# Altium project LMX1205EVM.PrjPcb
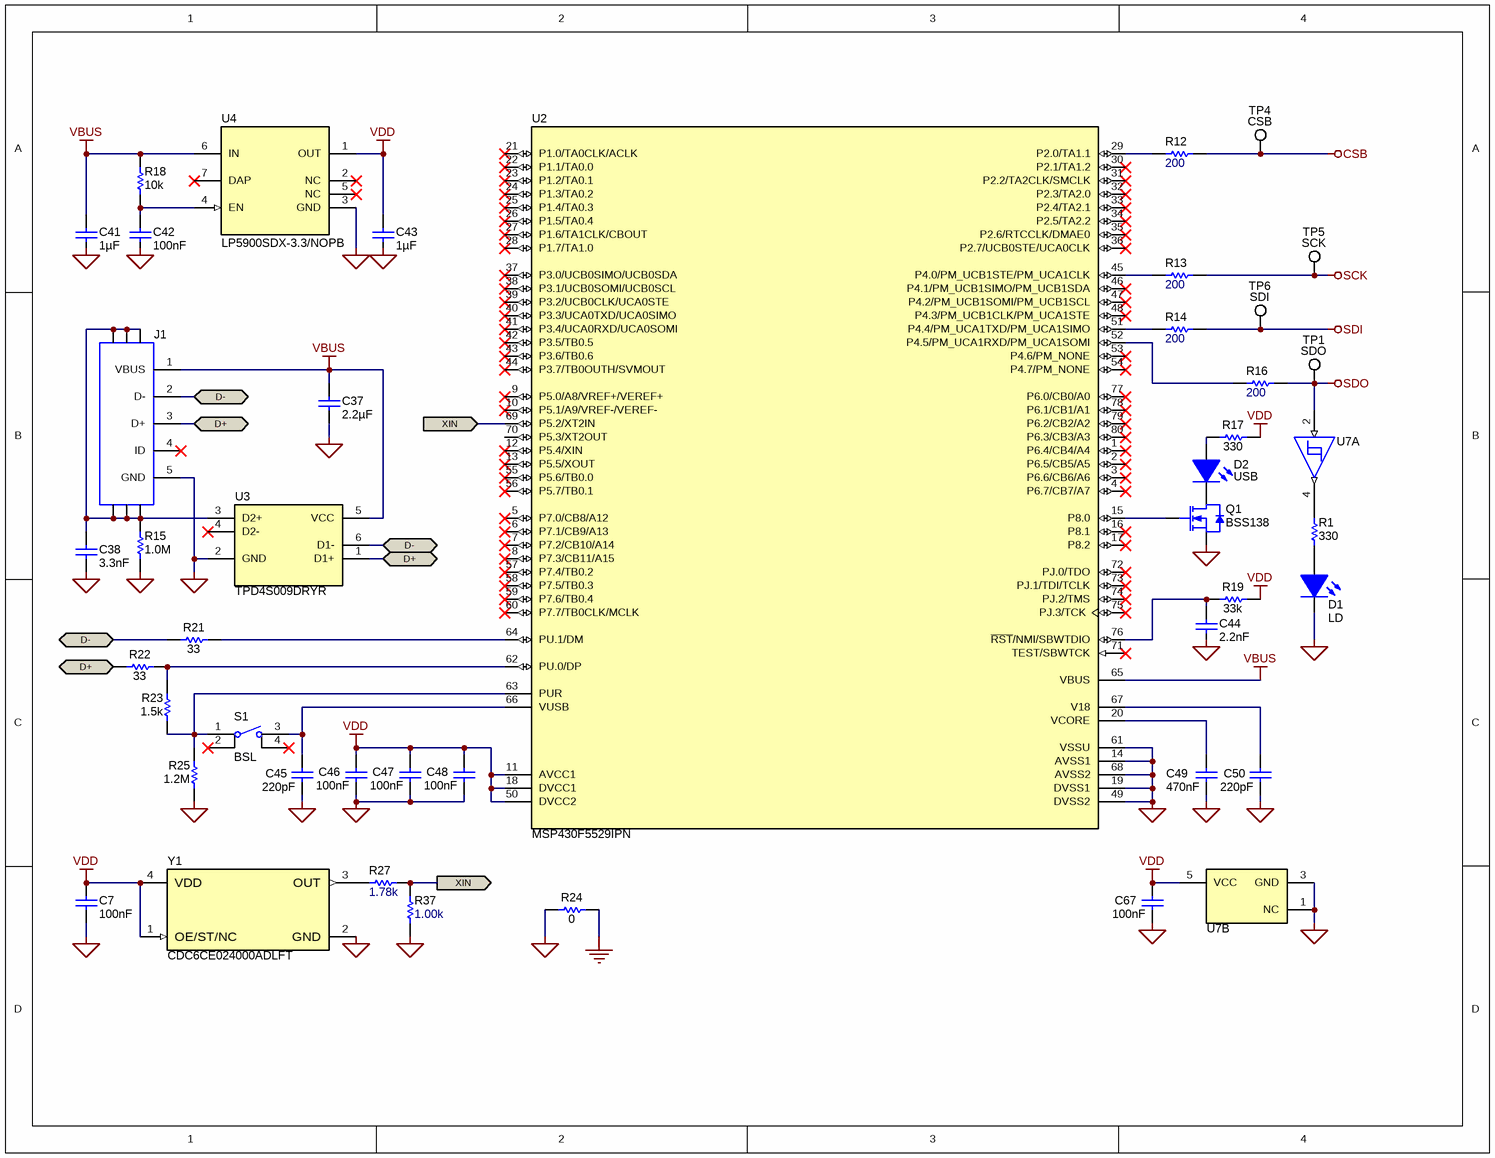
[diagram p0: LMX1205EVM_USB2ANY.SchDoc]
TID: N/A; TechSupport: http://www.ti.com/support; SCH_Rev: B; PRJ_Title: LMX1205EVM; PRJ_Customer: Public Release; PCB_Rev: B; CopyrightYear: 2024
4 sheets, 176 parts. Net scope: flat (ports and power ports of the same name join across sheets).
Board file: LMX1205EVM.PcbDoc
Sheets:
  LMX1205EVM_USB2ANY.SchDoc
  LMX1205EVM_PWR.SchDoc
  LMX1205EVM_BUF.SchDoc
  LMX1205EVM_Hardware.SchDoc

## Sheet LMX1205EVM_USB2ANY.SchDoc: USB2ANY
size Letter; Date: Not shown in title block; ApprovedBy: Not shown in title block; CheckedBy: Not shown in title block; Author: Not shown in title block; CompanyName: Not shown in title block; DrawnBy: Noel Fung; Engineer: Noel Fung; Organization: Not shown in title block; Address1: Not shown in title block; Address2: Not shown in title block; Address3: Not shown in title block; Address4: Not shown in title block; DocumentNumber: 1; Revision: Use project parameter SCH_Rev; SheetNumber: 1; SheetTotal: 4; PageSetup: Record=PageOptions¦CenterHorizontal=True¦CenterVertical=True¦PrintScale=1.00¦XCorrection=1.00¦YCorrection=1.00¦PrintKind=0¦BorderSize=5000000¦LeftOffset=0¦BottomOffset=0¦Orientation=2¦PaperLength=1000¦PaperWidth=1000¦Scale=100¦PaperSource=15¦PrintQuality=600¦MediaType=1¦DitherType=10¦PaperKind=Letter¦PrintScaleMode=1

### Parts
C7  Cap_F: 100nF  [0603]  (hidden comment: 885012206046)
C37  Cap_F: 2.2µF  [0603]  (hidden comment: 885012106018)
C38  Cap_F: 3.3nF  [0603]  (hidden comment: 885012206086)
C41  Cap_F: 1µF  [0603]  (hidden comment: 885012206052)
C42  Cap_F: 100nF  [0603]  (hidden comment: 885012206046)
C43  Cap_F: 1µF  [0603]  (hidden comment: 885012206052)
C44  Cap_F: 2.2nF  [0603]  (hidden comment: 885012206036)
C45  ValueDisplayed: 220pF  [0603]  (hidden comment: C0603C221J5GACTU)
C46  Cap_F: 100nF  [0603]  (hidden comment: 885012206046)
C47  Cap_F: 100nF  [0603]  (hidden comment: 885012206046)
C48  Cap_F: 100nF  [0603]  (hidden comment: 885012206046)
C49  Cap_F: 470nF  [0603]  (hidden comment: GRM188R71C474KA88D)
C50  ValueDisplayed: 220pF  [0603]  (hidden comment: C0603C221J5GACTU)
C67  Cap_F: 100nF  [0603]  (hidden comment: 885012206046)
D1  LD  [LED_LTST-C190]
D2  USB  [LED_LTST-C190]
J1  10118194-0001LF  [FCI_10118194-0001LF]  (value not drawn)
Q1  BSS138  [SOT-23]
R1  ValueDisplayed: 330  [0603]  (hidden comment: CRCW0603330RJNEA)
R12  ValueDisplayed: 200  [0603]  (hidden comment: CRCW0603200RFKEA)
R13  ValueDisplayed: 200  [0603]  (hidden comment: CRCW0603200RFKEA)
R14  ValueDisplayed: 200  [0603]  (hidden comment: CRCW0603200RFKEA)
R15  ValueDisplayed: 1.0M  [0603]  (hidden comment: CRCW06031M00JNEA)
R16  ValueDisplayed: 200  [0603]  (hidden comment: CRCW0603200RFKEA)
R17  ValueDisplayed: 330  [0603]  (hidden comment: CRCW0603330RJNEA)
R18  ValueDisplayed: 10k  [0603]  (hidden comment: CRCW060310K0JNEA)
R19  ValueDisplayed: 33k  [0603]  (hidden comment: CRCW060333K0JNEA)
R21  ValueDisplayed: 33  [0603]  (hidden comment: CRCW060333R0JNEA)
R22  ValueDisplayed: 33  [0603]  (hidden comment: CRCW060333R0JNEA)
R23  ValueDisplayed: 1.5k  [0603]  (hidden comment: CRCW06031K50JNEA)
R24  ValueDisplayed: 0  [0603]  (hidden comment: CRCW06030000Z0EA)
R25  ValueDisplayed: 1.2M  [0603]  (hidden comment: CRCW06031M20JNEA)
R27  ValueDisplayed: 1.78k  [0402]  (hidden comment: CRCW04021K78FKED)
R37  ValueDisplayed: 1.00k  [0402]  (hidden comment: CRCW04021K00FKED)
S1  BSL  [SW_FSM4JSMA]
TP1  SDO  [Keystone5002]
TP4  CSB  [Keystone5002]
TP5  SCK  [Keystone5002]
TP6  SDI  [Keystone5002]
U2  MSP430F5529IPN  [PN0080A_N]
U3  TPD4S009DRYR  [DRY0006A]
U4  LP5900SDX-3.3/NOPB  [NGF0006A]
U7  SN74LVC1G17DBVR  [DBV0005A_N]  (value not drawn)  (parts A,B of 2)
Y1  PartNumber: CDC6CE024000ADLFT  [DLF0004A-MFG]  (hidden comment: CDC6CXXXXXXXDLFT)

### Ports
D+ (bidir), D- (bidir), XIN (in), XIN (out)

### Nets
CSB: R12.2 TP4.1
DGND: C7.2 C37.2 C38.2 C41.2 C42.2 C43.2 C44.2 C45.2 C46.2 C47.2 C48.2 C49.2 C50.2 C67.2 D1.2(K) J1.5(GND) Q1.2(S) R15.1 R24.1 R25.1 R37.1 U2.14(AVSS1) U2.19(DVSS1) U2.49(DVSS2) U2.61(VSSU) U2.68(AVSS2) U3.2(GND) U4.3(GND) U7.1(NC) U7.3(GND) Y1.2(GND)
GND: R24.2
SCK: R13.2 TP5.1
SDI: R14.2 TP6.1
SDO: R16.2 TP1.1 U7.2(A)
VBUS: C37.1 C41.1 J1.1(VBUS) R18.2 U2.65(VBUS) U3.5(VCC) U4.6(IN)
VDD: C7.1 C43.1 C46.1 C47.1 C48.1 C67.1 R17.2 R19.2 U2.11(AVCC1) U2.18(DVCC1) U2.50(DVCC2) U4.1(OUT) U7.5(VCC) Y1.1(OE/ST/NC) Y1.4(VDD)
D+: J1.3(D+) R22.1 U3.1(D1+) ; port D+
D-: J1.2(D-) R21.1 U3.6(D1-) ; port D-
XIN: R27.2 R37.2 U2.69(P5.2/XT2IN) ; port XIN
NetC38_1: C38.1 J1.6 J1.7 J1.8 J1.9 J1.10 J1.11 R15.2 U3.3(D2+)
NetC42_1: C42.1 R18.1 U4.4(EN)
NetC44_1: C44.1 R19.1 U2.76(~{RST}/NMI/SBWTDIO)
NetC45_1: C45.1 S1.3 U2.66(VUSB)
NetC49_1: C49.1 U2.20(VCORE)
NetC50_1: C50.1 U2.67(V18)
NetD1_1: D1.1(A) R1.1
NetD2_1: D2.1(A) R17.1
NetD2_2: D2.2(K) Q1.3(D)
NetQ1_1: Q1.1(G) U2.15(P8.0)
NetR1_2: R1.2 U7.4(Y)
NetR12_1: R12.1 U2.29(P2.0/TA1.1)
NetR13_1: R13.1 U2.45(P4.0/PM_UCB1STE/PM_UCA1CLK)
NetR14_1: R14.1 U2.51(P4.4/PM_UCA1TXD/PM_UCA1SIMO)
NetR16_1: R16.1 U2.52(P4.5/PM_UCA1RXD/PM_UCA1SOMI)
NetR21_2: R21.2 U2.64(PU.1/DM)
NetR22_2: R22.2 R23.2 U2.62(PU.0/DP)
NetR23_1: R23.1 R25.2 S1.1 U2.63(PUR)
NetR27_1: R27.1 Y1.3(OUT)

Not connected (* = marked no-connect by the designer): J1 4(ID)*; S1 2* 4*; U2 1(P6.4/CB4/A4)* 2(P6.5/CB5/A5)* 3(P6.6/CB6/A6)* 4(P6.7/CB7/A7)* 5(P7.0/CB8/A12)* 6(P7.1/CB9/A13)* 7(P7.2/CB10/A14)* 8(P7.3/CB11/A15)* 9(P5.0/A8/VREF+/VEREF+)* 10(P5.1/A9/VREF-/VEREF-)* 12(P5.4/XIN)* 13(P5.5/XOUT)* 16(P8.1)* 17(P8.2)* 21(P1.0/TA0CLK/ACLK)* 22(P1.1/TA0.0)* 23(P1.2/TA0.1)* 24(P1.3/TA0.2)* 25(P1.4/TA0.3)* 26(P1.5/TA0.4)* 27(P1.6/TA1CLK/CBOUT)* 28(P1.7/TA1.0)* 30(P2.1/TA1.2)* 31(P2.2/TA2CLK/SMCLK)* 32(P2.3/TA2.0)* 33(P2.4/TA2.1)* 34(P2.5/TA2.2)* 35(P2.6/RTCCLK/DMAE0)* 36(P2.7/UCB0STE/UCA0CLK)* 37(P3.0/UCB0SIMO/UCB0SDA)* 38(P3.1/UCB0SOMI/UCB0SCL)* 39(P3.2/UCB0CLK/UCA0STE)* 40(P3.3/UCA0TXD/UCA0SIMO)* 41(P3.4/UCA0RXD/UCA0SOMI)* 42(P3.5/TB0.5)* 43(P3.6/TB0.6)* 44(P3.7/TB0OUTH/SVMOUT)* 46(P4.1/PM_UCB1SIMO/PM_UCB1SDA)* 47(P4.2/PM_UCB1SOMI/PM_UCB1SCL)* 48(P4.3/PM_UCB1CLK/PM_UCA1STE)* 53(P4.6/PM_NONE)* 54(P4.7/PM_NONE)* 55(P5.6/TB0.0)* 56(P5.7/TB0.1)* 57(P7.4/TB0.2)* 58(P7.5/TB0.3)* 59(P7.6/TB0.4)* 60(P7.7/TB0CLK/MCLK)* 70(P5.3/XT2OUT) 71(TEST/SBWTCK)* 72(PJ.0/TDO)* 73(PJ.1/TDI/TCLK)* 74(PJ.2/TMS)* 75(PJ.3/TCK)* 77(P6.0/CB0/A0)* 78(P6.1/CB1/A1)* 79(P6.2/CB2/A2)* 80(P6.3/CB3/A3)*; U3 4(D2-)*; U4 2(NC)* 5(NC)* 7(DAP)*

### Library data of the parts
C7 C42 C46-C48 C67 = CMP-0006829-4: CAP, CERM, 0.1 uF, 16 V, +/- 10%, X7R, 0603; Manufacturer: Wurth Elektronik; TaMin_C: -55°C; Polarized: N; SizeAreaWB_mm2: 4.68; Value1: Unknown; U/M: EA; Value: 0.1uF; TaMax_C: 125°C; SizeZ_mm: 1; SizeX_mm: 1.6; SizeY_mm: 0.8; Value2: 16V; SizeArea_mm2: 1.28; AEC Category: Q200
C37 = CMP-0006825-5: CAP, CERM, 2.2 uF, 16 V, +/- 20%, X5R, 0603; Manufacturer: Wurth Elektronik; TaMin_C: -55°C; Polarized: N; SizeAreaWB_mm2: 4.68; Value1: Unknown; U/M: EA; Value: 2.2uF; TaMax_C: 85°C; SizeZ_mm: 1; SizeX_mm: 1.6; SizeY_mm: 0.8; Value2: 16V; SizeArea_mm2: 1.28; AEC Category: Q200
C38 = CMP-0077942-1: CAP, CERM, 3300 pF, 50 V,+/- 10%, X7R, 0603; Manufacturer: Wurth Elektronik; TaMin_C: -55°C; Polarized: N; SizeAreaWB_mm2: 4.68; U/M: EA; Value: 3300pF; TaMax_C: 125°C; SizeZ_mm: 1; SizeX_mm: 1.6; SizeY_mm: 0.8; Value2: 50V; SizeArea_mm2: 1.28; AEC Category: Q200
C41 C43 = CMP-0006831-4: CAP, CERM, 1 uF, 16 V, +/- 10%, X7R, 0603; Manufacturer: Wurth Elektronik; TaMin_C: -55°C; Polarized: N; SizeAreaWB_mm2: 4.68; Value1: Unknown; U/M: EA; Value: 1uF; TaMax_C: 125°C; SizeZ_mm: 1; SizeX_mm: 1.6; SizeY_mm: 0.8; Value2: 16V; SizeArea_mm2: 1.28; AEC Category: Q200
C44 = CMP-0006827-4: CAP, CERM, 2200 pF, 16 V, +/- 10%, X7R, 0603; Manufacturer: Wurth Elektronik; TaMin_C: -55°C; Polarized: N; SizeAreaWB_mm2: 4.68; Value1: Unknown; U/M: EA; Value: 2200pF; TaMax_C: 125°C; SizeZ_mm: 1; SizeX_mm: 1.6; SizeY_mm: 0.8; Value2: 16V; SizeArea_mm2: 1.28; AEC Category: Q200
C45 C50 = CMP-0006893-4: CAP, CERM, 220 pF, 50 V, +/- 5%, C0G/NP0, 0603; Manufacturer: Kemet; TaMin_C: -55°C; Polarized: N; SizeAreaWB_mm2: 4.68; Value1: Unknown; U/M: EA; Value: 220pF; TaMax_C: 125°C; SizeZ_mm: 1; SizeX_mm: 1.6; SizeY_mm: 0.8; Value2: 50V; SizeArea_mm2: 1.28; AEC Category: Q200
C49 = CMP-0007398-4: CAP, CERM, 0.47 uF, 16 V, +/- 10%, X7R, 0603; Manufacturer: MuRata; TaMin_C: -55°C; Polarized: N; SizeAreaWB_mm2: 4.68; Value1: Unknown; U/M: EA; Value: 0.47uF; TaMax_C: 125°C; SizeZ_mm: 1; SizeX_mm: 1.6; SizeY_mm: 0.8; Value2: 16V; SizeArea_mm2: 1.28; AEC Category: Q200
D1 D2 = CMP-0002827-3: LED, Green, SMD; Manufacturer: Lite-On; PartNumber: LTST-C190GKT; Power_TotalModule: 100mW; Value2: 2.1V; Io_A: 20mA; Value1: 0.1W
J1 = CMP-0074596-2: Receptacle, USB 2.0, Micro-USB Type B, R/A, SMT; Manufacturer: FCI; CNHeader: False; Current_A: 1.8A; Gender: Female; Voltage_V: 100V; Row_Count: 1; Pitch_mm: 0.65; ContactFinish: Gold; CT: True; Cert_UL: Y
Q1 = CMP-0000755-1: MOSFET, N-CH, 50 V, 0.22 A, SOT-23; Alternate Manufacturer: None; Manufacturer: Fairchild Semiconductor; SizeZ_mm: 1.1; ChType: N; Value2: 1.7 nC; VdsMax_V: 50V; SizeX_mm: 2.5; SizeY_mm: 3; Vgs_V: 20V; Value: 50V; Rdson45_ohm: 6; SizeArea_mm2: 7.5; AEC Category: Q101; IdsMax_A: 220mA; SizeAreaWB_mm2: 14; U/M: EA; QgTyp_nC: 1.7
R1 R17 = CMP-0025785-4: RES, 330, 5%, 0.1 W, AEC-Q200 Grade 0, 0603; Manufacturer: Vishay-Dale; Power_W: 100mW; TempCo: 200 ppm/C; Value_Code: 330R; Value: 330; EIA_Code: E24; SizeX_mm: 1.6; SizeY_mm: 0.8; SizeZ_mm: 1; Value2: 0.1W; SizeArea_mm2: 1.28; AEC Qualified: Y; VDC_V: 75V; AEC Category: Q200; AEC Grade: 0
R12-R14 R16 = CMP-0022201-5: RES, 200, 1%, 0.1 W, AEC-Q200 Grade 0, 0603; Manufacturer: Vishay-Dale; Power_W: 100mW; TempCo: 100 ppm/C; Value_Code: 200R; Value: 200; EIA_Code: E96; SizeX_mm: 1.6; SizeY_mm: 0.8; SizeZ_mm: 1; Value2: 0.1W; SizeArea_mm2: 1.28; AEC Qualified: Y; VDC_V: 75V; AEC Category: Q200; AEC Grade: 0
R15 = CMP-0025736-4: RES, 1.0 M, 5%, 0.1 W, AEC-Q200 Grade 0, 0603; Manufacturer: Vishay-Dale; Power_W: 100mW; TempCo: 200 ppm/C; Value_Code: 1M00; Value: 1.0Meg; EIA_Code: E24; Res_ohm: 1M; SizeX_mm: 1.6; SizeY_mm: 0.8; SizeZ_mm: 1; Value2: 0.1W; SizeArea_mm2: 1.28; AEC Qualified: Y; VDC_V: 75V; AEC Category: Q200; AEC Grade: 0
R18 = CMP-0025701-4: RES, 10 k, 5%, 0.1 W, AEC-Q200 Grade 0, 0603; Manufacturer: Vishay-Dale; Power_W: 100mW; TempCo: 200 ppm/C; Value_Code: 10k0; Value: 10k; EIA_Code: E24; SizeX_mm: 1.6; SizeY_mm: 0.8; SizeZ_mm: 1; Value2: 0.1W; SizeArea_mm2: 1.28; AEC Qualified: Y; VDC_V: 75V; AEC Category: Q200; AEC Grade: 0
R19 = CMP-0025786-4: RES, 33 k, 5%, 0.1 W, AEC-Q200 Grade 0, 0603; Manufacturer: Vishay-Dale; Power_W: 100mW; TempCo: 200 ppm/C; Value_Code: 33k0; Value: 33k; EIA_Code: E24; SizeX_mm: 1.6; SizeY_mm: 0.8; SizeZ_mm: 1; Value2: 0.1W; SizeArea_mm2: 1.28; AEC Qualified: Y; VDC_V: 75V; AEC Category: Q200; AEC Grade: 0
R21 R22 = CMP-0025787-4: RES, 33, 5%, 0.1 W, AEC-Q200 Grade 0, 0603; Manufacturer: Vishay-Dale; Power_W: 100mW; TempCo: 200 ppm/C; Value_Code: 33R0; Value: 33; EIA_Code: E24; SizeX_mm: 1.6; SizeY_mm: 0.8; SizeZ_mm: 1; Value2: 0.1W; SizeArea_mm2: 1.28; AEC Qualified: Y; VDC_V: 75V; AEC Category: Q200; AEC Grade: 0
R23 = CMP-0025733-4: RES, 1.5 k, 5%, 0.1 W, AEC-Q200 Grade 0, 0603; Manufacturer: Vishay-Dale; Power_W: 100mW; TempCo: 200 ppm/C; Value_Code: 1k50; Value: 1.5k; EIA_Code: E24; SizeX_mm: 1.6; SizeY_mm: 0.8; SizeZ_mm: 1; Value2: 0.1W; SizeArea_mm2: 1.28; AEC Qualified: Y; VDC_V: 75V; AEC Category: Q200; AEC Grade: 0
R24 = CMP-0025697-4: RES, 0, 5%, 0.1 W, AEC-Q200 Grade 0, 0603; Manufacturer: Vishay-Dale; Power_W: 100mW; TempCo: 200 ppm/C; Value_Code: 0000; Value: 0; EIA_Code: E24; SizeX_mm: 1.6; SizeY_mm: 0.8; SizeZ_mm: 1; Value2: 0.1W; SizeArea_mm2: 1.28; AEC Qualified: Y; VDC_V: 75V; AEC Category: Q200
R25 = CMP-0025738-4: RES, 1.2 M, 5%, 0.1 W, AEC-Q200 Grade 0, 0603; Manufacturer: Vishay-Dale; Power_W: 100mW; TempCo: 200 ppm/C; Value_Code: 1M20; Value: 1.2Meg; EIA_Code: E24; SizeX_mm: 1.6; SizeY_mm: 0.8; SizeZ_mm: 1; Value2: 0.1W; SizeArea_mm2: 1.28; AEC Qualified: Y; VDC_V: 75V; AEC Category: Q200; AEC Grade: 0
R27 = CMP-0026095-2: RES, 1.78 k, 1%, 0.063 W, AEC-Q200 Grade 0, 0402; Manufacturer: Vishay-Dale; Power_W: 63mW; TempCo: 100 ppm/C; Value_Code: 1k78; Value: 1.78k; EIA_Code: E96; SizeX_mm: 1; SizeY_mm: 0.5; SizeZ_mm: 0.6; Value2: 0.063W; AEC Qualified: Y; VDC_V: 50V; AEC Category: Q200; AEC Grade: 0
R37 = CMP-0026071-3: RES, 1.00 k, 1%, 0.063 W, AEC-Q200 Grade 0, 0402; Manufacturer: Vishay-Dale; Power_W: 63mW; TempCo: 100 ppm/C; Value_Code: 1k00; Value: 1.00k; EIA_Code: E96; Res_ohm: 1k; SizeX_mm: 1; SizeY_mm: 0.5; SizeZ_mm: 0.6; Value2: 0.063W; AEC Qualified: Y; VDC_V: 50V; AEC Category: Q200; AEC Grade: 0
S1 = CMP-0002134-3: Switch, Tactile, SPST-NO, 0.05A, 12V, SMT; PartNumber: FSM4JSMA; Manufacturer: TE Connectivity; CurrentRating_mA: 50A; PositionCount: 1; SwitchFunction: Off-Mom
TP1 TP4-TP6 = CMP-0055139-2: Test Point, Miniature, White, TH; Manufacturer: Keystone Electronics; CNHeader: FALSE; Green_Lifecycle: Active; Green_REACh: Passed; ContactFinish: Silver; CT: TRUE
U2 = CMP-0038965-1: 25 MHz Mixed Signal Microcontroller with 128 KB Flash, 8192 B SRAM and 63 GPIOs, -40 to 85 degC, 80-pin QFP (PN), Green (RoHS & no Sb/Br); Manufacturer: Texas Instruments; Real-Time Clock: Yes; Multiplier: 32x32; Frequency(MHz): 25; USCI_A (UART/LIN/IrDA/SPI): 2; SubFamily: 5 Series; Timers - 16-bit: 4; ADC Channels: 16; GPIO: 63; SRAM(B): 8192; DMA: 3; ADC: 12-bit SAR; Flash(KB): 128; USB: 1
U3 = CMP-0043120-3: 4-Channel ESD Solution for High-Speed Differential Interface, DRY0006A (USON-6); Manufacturer: Texas Instruments; Eco-Plan: Green (RoHS & no Sb/Br); Differential Capacitance(pF): 0.05; IEC 61000-4-2 Contact(+/- kV): 8; IO Capacitance(Typ)(pF): 0.8; Breakdown Voltage(Min)(V): 9; IO Leakage Current(nA): Jan-00; AEC Category: Q200; AEC Qualified: N; CompType: IC; SizeAreaWB_mm2: 4.9; SizeArea_mm2: 1.45; SizeX_mm: 1.0; SizeZ_mm: 0.6; Rating: Catalog
U4 = CMP-0070655-2: Ultra Low Noise, 150mA Linear Regulator for RF/Analog Circuits Requires No Bypass Capacitor, 6-pin LLP, Pb-Free; Manufacturer: Texas Instruments; PackageTopMarking: XTT*L16; CompType: LDO IC; PowerWise: N
U7 = CMP-0051702-2: Single Schmitt-Trigger Buffer, DBV0005A, LARGE T&R; Manufacturer: Texas Instruments; Output Drive (IOL/IOH)(Max)(mA): 32/-32; Technology Family: LVC; ICC @ Nom Voltage(Max)(mA): 0.01; VCC(Min)(V): 1.65; F @ Nom Voltage(Max)(Mhz): 150; Schmitt Trigger: Yes; Voltage(Nom)(V): 1.8,2.5,3.3,5; 3-State Output: No; Bits(#): 1; VCC(Max)(V): 5.5; Input Type: CMOS/TTL; Logic: True; tpd @ Nom Voltage(Max)(ns): 11,6.5,5.5,5; Output Type: CMOS; Rating: Catalog; Sub-Family: Non-Inverting Buffer/Driver; AEC Category: Q200; AEC Qualified: N; CompType: IC; SizeX_mm: 2.8; SizeY_mm: 2.9; SizeZ_mm: 1.45
Y1 = CMP-0097145-1: High-Performance BAW Oscillator; Manufacturer: Texas Instruments; Alternate PartNumber: LMK6CE02400CDLF; Min Supply Voltage: 1.62V; Frequency Stability: 25ppm; AEC Qualified: No; Max Supply Voltage: 3.63V; Standoff Height: 0mm; SizeZ_mm: 1mm; TJmax_C: +130°C

## Sheet LMX1205EVM_PWR.SchDoc: PowerSupply
size Letter; Date: Not shown in title block; ApprovedBy: Not shown in title block; CheckedBy: Not shown in title block; Author: Not shown in title block; CompanyName: Not shown in title block; DrawnBy: Noel Fung; Engineer: Noel Fung; Organization: Not shown in title block; Address1: Not shown in title block; Address2: Not shown in title block; Address3: Not shown in title block; Address4: Not shown in title block; DocumentNumber: 2; Revision: Use project parameter SCH_Rev; SheetNumber: 2; SheetTotal: 4; PageSetup: Record=PageOptions¦CenterHorizontal=True¦CenterVertical=True¦PrintScale=1.00¦XCorrection=1.00¦YCorrection=1.00¦PrintKind=0¦BorderSize=5000000¦LeftOffset=0¦BottomOffset=0¦Orientation=2¦PaperLength=1000¦PaperWidth=1000¦Scale=100¦PaperSource=15¦PrintQuality=600¦MediaType=1¦DitherType=10¦PaperKind=Letter¦PrintScaleMode=1
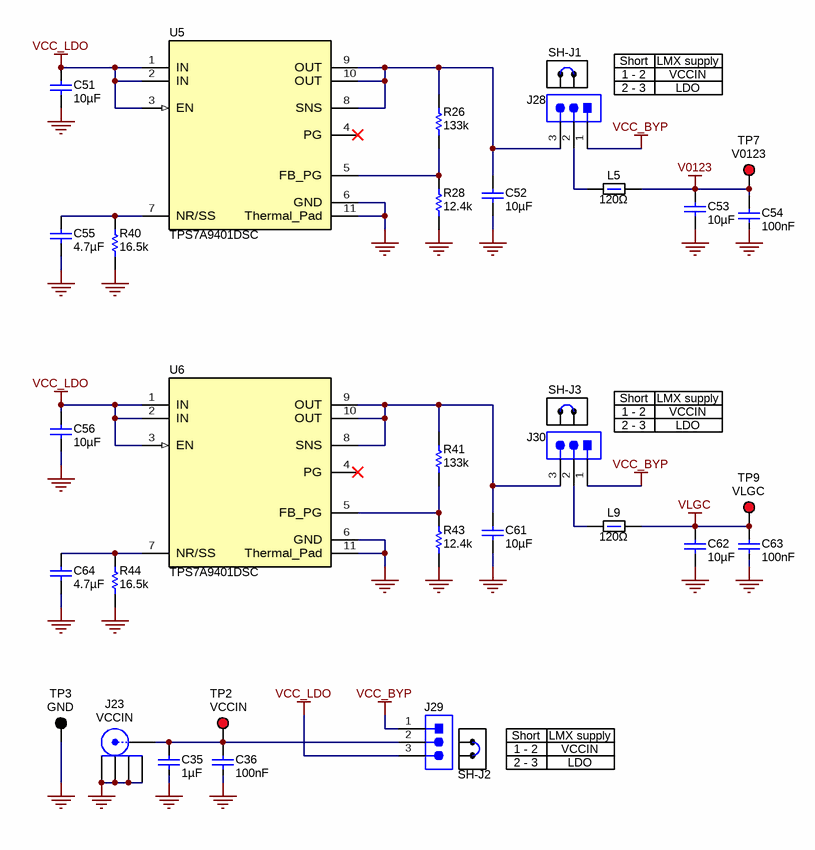
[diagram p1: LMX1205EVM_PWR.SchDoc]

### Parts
C35  Cap_F: 1µF  [0603]  (hidden comment: 885012206052)
C36  Cap_F: 100nF  [0603]  (hidden comment: 885012206046)
C51  ValueDisplayed: 10µF  [0603]  (hidden comment: GRM188R61A106KAALD)
C52  ValueDisplayed: 10µF  [0603]  (hidden comment: GRM188R61A106KAALD)
C53  ValueDisplayed: 10µF  [0603]  (hidden comment: GRM188R61A106KAALD)
C54  Cap_F: 100nF  [0603]  (hidden comment: 885012206046)
C55  Cap_F: 4.7µF  [0603]  (hidden comment: GRM188Z71C475KE21D)
C56  ValueDisplayed: 10µF  [0603]  (hidden comment: GRM188R61A106KAALD)
C61  ValueDisplayed: 10µF  [0603]  (hidden comment: GRM188R61A106KAALD)
C62  ValueDisplayed: 10µF  [0603]  (hidden comment: GRM188R61A106KAALD)
C63  Cap_F: 100nF  [0603]  (hidden comment: 885012206046)
C64  Cap_F: 4.7µF  [0603]  (hidden comment: GRM188Z71C475KE21D)
J23  VCCIN  [FP-CON-SMA-EDGE-S_CONN_JACK-MFG]
J28  TSW-103-07-G-S  [TSW-103-07-G-S]  (value not drawn)
J29  TSW-103-07-G-S  [TSW-103-07-G-S]  (value not drawn)
J30  TSW-103-07-G-S  [TSW-103-07-G-S]  (value not drawn)
L5  120Ω  [0603]
L9  120Ω  [0603]
R26  ValueDisplayed: 133k  [0603]  (hidden comment: CRCW0603133KFKEA)
R28  ValueDisplayed: 12.4k  [0603]  (hidden comment: CRCW060312K4FKEA)
R40  ValueDisplayed: 16.5k  [0603]  (hidden comment: CRCW060316K5FKEA)
R41  ValueDisplayed: 133k  [0603]  (hidden comment: CRCW0603133KFKEA)
R43  ValueDisplayed: 12.4k  [0603]  (hidden comment: CRCW060312K4FKEA)
R44  ValueDisplayed: 16.5k  [0603]  (hidden comment: CRCW060316K5FKEA)
SH-J1  SNT-100-BK-G  [SNT-100-BK-G]  (value not drawn)
SH-J2  SNT-100-BK-G  [SNT-100-BK-G]  (value not drawn)
SH-J3  SNT-100-BK-G  [SNT-100-BK-G]  (value not drawn)
TP2  VCCIN  [Keystone5000]
TP3  GND  [Keystone5001]
TP7  V0123  [Keystone5000]
TP9  VLGC  [Keystone5000]
U5  TPS7A9401DSC  [DSC0010J-MFG]
U6  TPS7A9401DSC  [DSC0010J-MFG]

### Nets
GND: C35.2 C36.2 C51.2 C52.2 C53.1 C54.2 C55.2 C56.2 C61.2 C62.1 C63.2 C64.2 J23.2 J23.3 J23.4 J23.5 R28.1 R40.1 R43.1 R44.1 TP3.1 U5.6(GND) U5.11(Thermal_Pad) U6.6(GND) U6.11(Thermal_Pad)
V0123: C53.2 C54.1 L5.2 TP7.1
VCC_BYP: J28.1 J29.1 J30.1
VCC_LDO: C51.1 C56.1 J29.3 U5.1(IN) U5.2(IN) U5.3(EN) U6.1(IN) U6.2(IN) U6.3(EN)
VLGC: C62.2 C63.1 L9.2 TP9.1
NetC35_1: C35.1 C36.1 J23.1 J29.2 TP2.1
NetC52_1: C52.1 J28.3 R26.2 U5.8(SNS) U5.9(OUT) U5.10(OUT)
NetC55_1: C55.1 R40.2 U5.7(NR/SS)
NetC61_1: C61.1 J30.3 R41.2 U6.8(SNS) U6.9(OUT) U6.10(OUT)
NetC64_1: C64.1 R44.2 U6.7(NR/SS)
NetJ28_2: J28.2 L5.1
NetJ30_2: J30.2 L9.1
NetR26_1: R26.1 R28.2 U5.5(FB_PG)
NetR41_1: R41.1 R43.2 U6.5(FB_PG)

Not connected (* = marked no-connect by the designer): U5 4(PG)*; U6 4(PG)*

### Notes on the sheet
- Short
- 1 - 2
- LMX supply
- VCCIN
- 2 - 3
- LDO
- (near SH-J2) Short
- (near SH-J2) 1 - 2
- (near SH-J2) 2 - 3

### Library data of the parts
C35 = CMP-0006831-4: as C41 on sheet LMX1205EVM_USB2ANY
C36 C54 C63 = CMP-0006829-4: as C7 on sheet LMX1205EVM_USB2ANY
C51-C53 C56 C61 C62 = CMP-0086193-1: CAP, CERM, 10 µF, 10 V,+/- 10%, X5R, 0603; Manufacturer: MuRata; SizeY_mm: 0.8; SizeAreaWB_mm2: 4.68; SizeX_mm: 1.6; SizeArea_mm2: 1.28; VDC_V: 10V; AEC Qualified: N; Value: 10uF; U/M: EA; SizeZ_mm: 1; TaMax_C: 85°C; AEC Category: Q200; TaMin_C: -55°C
C55 C64 = CMP-0064936-4: CAP, CERM, 4.7 uF, 16 V,+/- 10%, X7R, 0603; Manufacturer: MuRata; TaMin_C: -55°C; Polarized: N; SizeAreaWB_mm2: 4.68; Value1: Unknown; U/M: EA; Value: 4.7uF; TaMax_C: 125°C; SizeZ_mm: 1; SizeX_mm: 1.6; SizeY_mm: 0.8; Value2: 16V; SizeArea_mm2: 1.28; AEC Category: Q200
J23 = CMP-0088000-4: CONN SMA JACK STR EDGE MNT; Manufacturer: RF Solutions Ltd.; PartNumber: CON-SMA-EDGE-S; ContactFinish: Gold; Shrouded: true
J28-J30 = CMP-0075407-2: Header, 100mil, 3x1, Gold, TH; Manufacturer: Samtec; Pitch_mm: 2.54; Cert_VDE: N; Gender: Male; Cert_CSA: Y; Voltage_V: 550V; Green_REACh: Passed; Current_A: 6.3A; Green_Lifecycle: Active; Row_Count: 1
L5 L9 = CMP-0003352-2: Ferrite Bead, 120 ohm @ 100 MHz, 3 A, 0603; Manufacturer: MuRata; PartNumber: BLM18SG121TN1D; ZTyp@100MHz_Ohm: 120; SizeAreaWB_mm2: 4.68; DCR_ohm: 0.025; Value1: 0.025 ohm; Value: 120 ohm; Imax_A: 3A; SizeZ_mm: 1; SizeX_mm: 1.6; SizeY_mm: 0.8; SizeArea_mm2: 1.28
R26 R41 = CMP-0022038-4: RES, 133 k, 1%, 0.1 W, AEC-Q200 Grade 0, 0603; Manufacturer: Vishay-Dale; Power_W: 100mW; TempCo: 100 ppm/C; Value: 133k; EIA_Code: E96; SizeX_mm: 1.6; SizeY_mm: 0.8; SizeZ_mm: 1; Value2: 0.1W; SizeArea_mm2: 1.28; AEC Qualified: Y; VDC_V: 75V; AEC Category: Q200; AEC Grade: 0
R28 R43 = CMP-0022031-4: RES, 12.4 k, 1%, 0.1 W, AEC-Q200 Grade 0, 0603; Manufacturer: Vishay-Dale; Power_W: 100mW; TempCo: 100 ppm/C; Value_Code: 12k4; Value: 12.4k; EIA_Code: E96; SizeX_mm: 1.6; SizeY_mm: 0.8; SizeZ_mm: 1; Value2: 0.1W; SizeArea_mm2: 1.28; AEC Qualified: Y; VDC_V: 75V; AEC Category: Q200; AEC Grade: 0
R40 R44 = CMP-0022080-4: RES, 16.5 k, 1%, 0.1 W, AEC-Q200 Grade 0, 0603; Manufacturer: Vishay-Dale; Power_W: 100mW; TempCo: 100 ppm/C; Value_Code: 16k5; Value: 16.5k; EIA_Code: E96; SizeX_mm: 1.6; SizeY_mm: 0.8; SizeZ_mm: 1; Value2: 0.1W; SizeArea_mm2: 1.28; AEC Qualified: Y; VDC_V: 75V; AEC Category: Q200; AEC Grade: 0
SH-J1-SH-J3 = CMP-0003623-3: Shunt, 100mil, Gold plated, Black; Alternate PartNumber: 969102-0000-DA; Manufacturer: Samtec; Alternate Manufacturer: 3M; Value: 1x2; Note: You can "mate" this to a header by matching the designator.  i.e. use SH-J3 for header J3
TP2 TP7 TP9 = CMP-0055137-2: Test Point, Miniature, Red, TH; Manufacturer: Keystone Electronics; CNHeader: FALSE; Green_Lifecycle: Active; Green_REACh: Passed; ContactFinish: Silver; CT: TRUE
TP3 = CMP-0055138-2: Test Point, Miniature, Black, TH; Manufacturer: Keystone Electronics; CNHeader: FALSE; Green_Lifecycle: Active; Green_REACh: Passed; ContactFinish: Silver; CT: TRUE
U5 U6 = CMP-0091022-1: 1-A, Ultra-Low Noise, Ultra-High PSRR, RF Voltage Regulator; Manufacturer: Texas Instruments; Max Supply Voltage: 5.5V; Accuracy Percentage: 1-1.5%; SizeZ_mm: 0.8mm; Output Type: AdjustableProgrammable; Min Supply Voltage: 1.7V; TJmax_C: +150°C; Dropout Voltage: 210mV; AEC Qualified: No; Standoff Height: 0mm; Output Voltage: 0.4-5.3V; Number Of Outputs: 1; Nominal Supply Current: 15-47mA

## Sheet LMX1205EVM_BUF.SchDoc: RF Buffer
size Letter; Date: Not shown in title block; ApprovedBy: Not shown in title block; CheckedBy: Not shown in title block; Author: Not shown in title block; CompanyName: Not shown in title block; DrawnBy: Noel Fung; Engineer: Noel Fung; Organization: Not shown in title block; Address1: Not shown in title block; Address2: Not shown in title block; Address3: Not shown in title block; Address4: Not shown in title block; DocumentNumber: 3; Revision: Use project parameter SCH_Rev; SheetNumber: 3; SheetTotal: 4; PageSetup: Record=PageOptions¦CenterHorizontal=True¦CenterVertical=True¦PrintScale=1.00¦XCorrection=1.00¦YCorrection=1.00¦PrintKind=0¦BorderSize=5000000¦LeftOffset=0¦BottomOffset=0¦Orientation=2¦PaperLength=1000¦PaperWidth=1000¦Scale=100¦PaperSource=15¦PrintQuality=600¦MediaType=1¦DitherType=10¦PaperKind=Letter¦PrintScaleMode=1
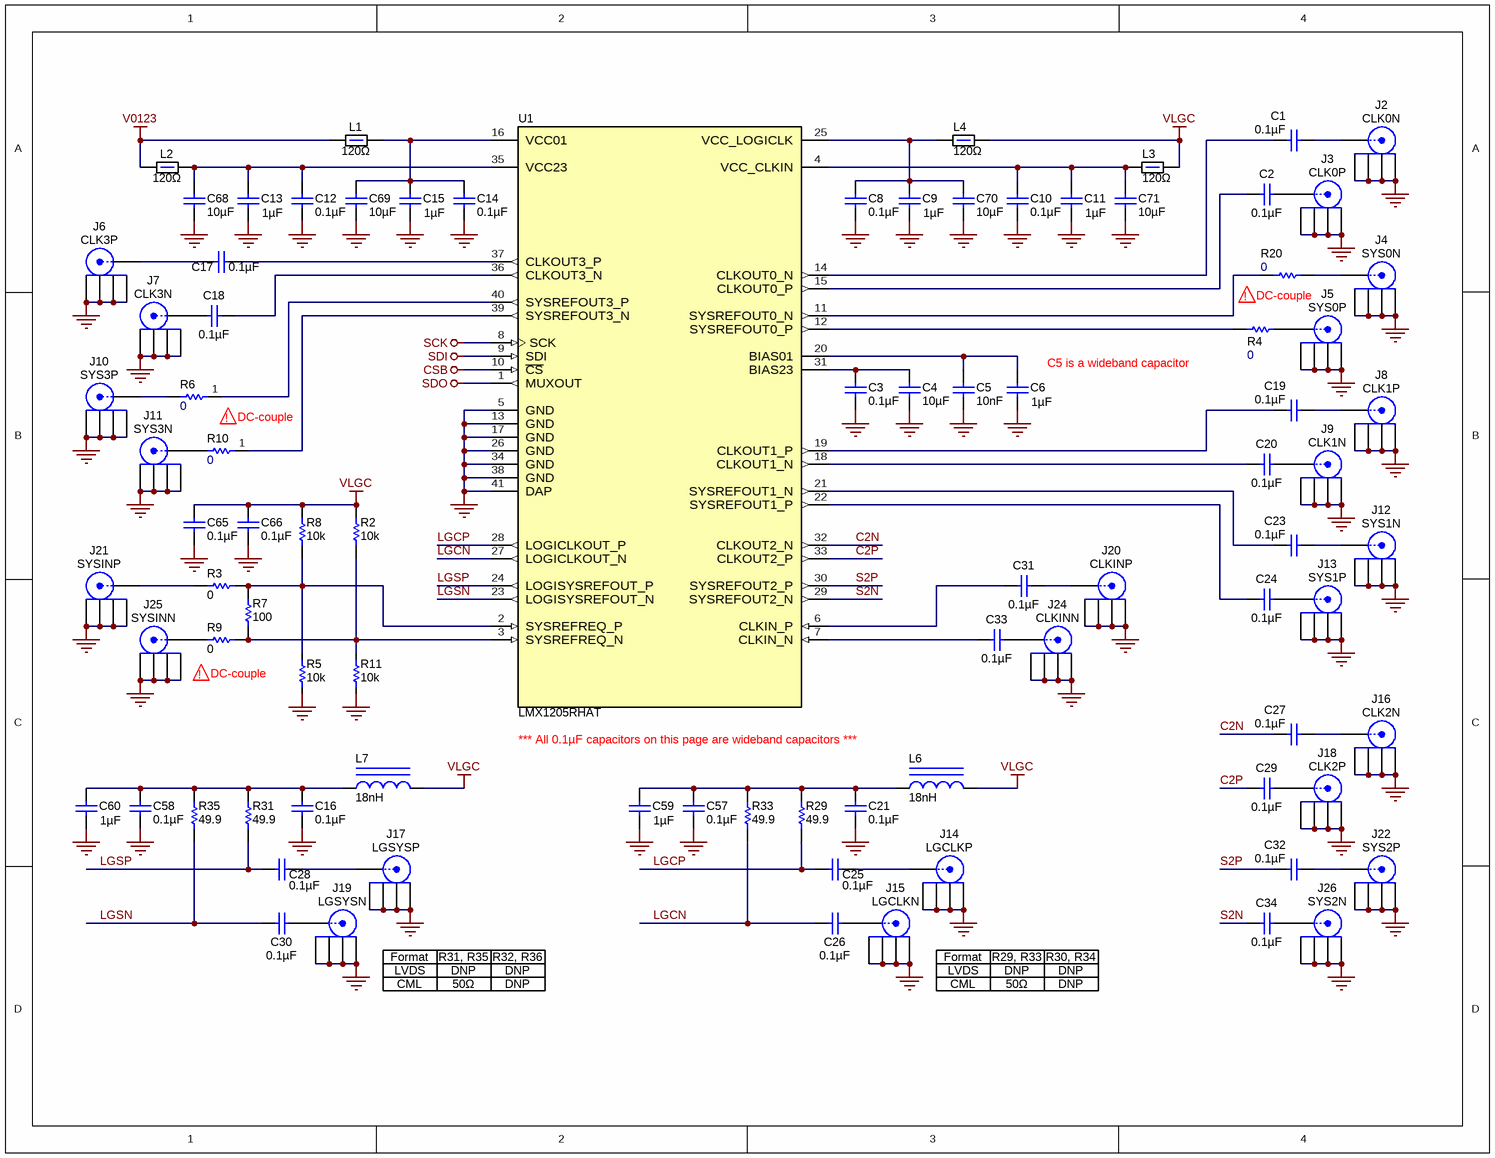
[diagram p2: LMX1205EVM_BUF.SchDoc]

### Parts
C1  ValueDisplayed: 0.1µF  [0201_033L]  (hidden comment: ATC530Z104KT10T)
C2  ValueDisplayed: 0.1µF  [0201_033L]  (hidden comment: ATC530Z104KT10T)
C3  ValueDisplayed: 0.1µF  [0201_033L]  (hidden comment: ATC530Z104KT10T)
C4  ValueDisplayed: 10µF  [0603L]  (hidden comment: GRM188R61A106KAALD)
C5  ValueDisplayed: 10nF  [0201_033L]  (hidden comment: 550Z103PTT)
C6  ValueDisplayed: 1µF  [0402S]  (hidden comment: GRM155R61E105KA12D)
C8  ValueDisplayed: 0.1µF  [0201_033L]  (hidden comment: ATC530Z104KT10T)
C9  ValueDisplayed: 1µF  [0402S]  (hidden comment: GRM155R61E105KA12D)
C10  ValueDisplayed: 0.1µF  [0201_033L]  (hidden comment: ATC530Z104KT10T)
C11  ValueDisplayed: 1µF  [0402S]  (hidden comment: GRM155R61E105KA12D)
C12  ValueDisplayed: 0.1µF  [0201_033L]  (hidden comment: ATC530Z104KT10T)
C13  ValueDisplayed: 1µF  [0402S]  (hidden comment: GRM155R61E105KA12D)
C14  ValueDisplayed: 0.1µF  [0201_033L]  (hidden comment: ATC530Z104KT10T)
C15  ValueDisplayed: 1µF  [0402S]  (hidden comment: GRM155R61E105KA12D)
C16  ValueDisplayed: 0.1µF  [0201_033L]  (hidden comment: ATC530Z104KT10T)
C17  ValueDisplayed: 0.1µF  [0201_033L]  (hidden comment: ATC530Z104KT10T)
C18  ValueDisplayed: 0.1µF  [0201_033L]  (hidden comment: ATC530Z104KT10T)
C19  ValueDisplayed: 0.1µF  [0201_033L]  (hidden comment: ATC530Z104KT10T)
C20  ValueDisplayed: 0.1µF  [0201_033L]  (hidden comment: ATC530Z104KT10T)
C21  ValueDisplayed: 0.1µF  [0201_033L]  (hidden comment: ATC530Z104KT10T)
C23  ValueDisplayed: 0.1µF  [0201_033L]  (hidden comment: ATC530Z104KT10T)
C24  ValueDisplayed: 0.1µF  [0201_033L]  (hidden comment: ATC530Z104KT10T)
C25  ValueDisplayed: 0.1µF  [0201_033L]  (hidden comment: ATC530Z104KT10T)
C26  ValueDisplayed: 0.1µF  [0201_033L]  (hidden comment: ATC530Z104KT10T)
C27  ValueDisplayed: 0.1µF  [0201_033L]  (hidden comment: ATC530Z104KT10T)
C28  ValueDisplayed: 0.1µF  [0201_033L]  (hidden comment: ATC530Z104KT10T)
C29  ValueDisplayed: 0.1µF  [0201_033L]  (hidden comment: ATC530Z104KT10T)
C30  ValueDisplayed: 0.1µF  [0201_033L]  (hidden comment: ATC530Z104KT10T)
C31  ValueDisplayed: 0.1µF  [0201_033L]  (hidden comment: ATC530Z104KT10T)
C32  ValueDisplayed: 0.1µF  [0201_033L]  (hidden comment: ATC530Z104KT10T)
C33  ValueDisplayed: 0.1µF  [0201_033L]  (hidden comment: ATC530Z104KT10T)
C34  ValueDisplayed: 0.1µF  [0201_033L]  (hidden comment: ATC530Z104KT10T)
C57  ValueDisplayed: 0.1µF  [0201_033L]  (hidden comment: ATC530Z104KT10T)
C58  ValueDisplayed: 0.1µF  [0201_033L]  (hidden comment: ATC530Z104KT10T)
C59  ValueDisplayed: 1µF  [0402S]  (hidden comment: GRM155R61E105KA12D)
C60  ValueDisplayed: 1µF  [0402S]  (hidden comment: GRM155R61E105KA12D)
C65  ValueDisplayed: 0.1µF  [0201_033L]  (hidden comment: ATC530Z104KT10T)
C66  ValueDisplayed: 0.1µF  [0201_033L]  (hidden comment: ATC530Z104KT10T)
C68  ValueDisplayed: 10µF  [0603]  (hidden comment: GRM188R61A106KAALD)
C69  ValueDisplayed: 10µF  [0603]  (hidden comment: GRM188R61A106KAALD)
C70  ValueDisplayed: 10µF  [0603]  (hidden comment: GRM188R61A106KAALD)
C71  ValueDisplayed: 10µF  [0603]  (hidden comment: GRM188R61A106KAALD)
J2  CLK0N  [Johnson_142-0761-881]
J3  CLK0P  [Johnson_142-0761-881]
J4  SYS0N  [Johnson_142-0761-881]
J5  SYS0P  [Johnson_142-0761-881]
J6  CLK3P  [Johnson_142-0761-881]
J7  CLK3N  [Johnson_142-0761-881]
J8  CLK1P  [Johnson_142-0761-881]
J9  CLK1N  [Johnson_142-0761-881]
J10  SYS3P  [Johnson_142-0761-881]
J11  SYS3N  [Johnson_142-0761-881]
J12  SYS1N  [Johnson_142-0761-881]
J13  SYS1P  [Johnson_142-0761-881]
J14  LGCLKP  [FP-CON-SMA-EDGE-S_CONN_JACK-MFG]
J15  LGCLKN  [FP-CON-SMA-EDGE-S_CONN_JACK-MFG]
J16  CLK2N  [Johnson_142-0761-881]
J17  LGSYSP  [FP-CON-SMA-EDGE-S_CONN_JACK-MFG]
J18  CLK2P  [Johnson_142-0761-881]
J19  LGSYSN  [FP-CON-SMA-EDGE-S_CONN_JACK-MFG]
J20  CLKINP  [Johnson_142-0761-881]
J21  SYSINP  [Johnson_142-0761-881]
J22  SYS2P  [Johnson_142-0761-881]
J24  CLKINN  [Johnson_142-0761-881]
J25  SYSINN  [Johnson_142-0761-881]
J26  SYS2N  [Johnson_142-0761-881]
L1  120Ω  [0603]
L2  120Ω  [0603]
L3  120Ω  [0603]
L4  120Ω  [0603]
L6  ValueDisplayed: 18nH  [IND_LQG15H]  (hidden comment: LQG15HS18NJ02D)
L7  ValueDisplayed: 18nH  [IND_LQG15H]  (hidden comment: LQG15HS18NJ02D)
R2  ValueDisplayed: 10k  [0402S]  (hidden comment: CRCW040210K0JNED)
R3  ValueDisplayed: 0  [0402S]  (hidden comment: CRCW04020000Z0ED)
R4  ValueDisplayed: 0  [0201L]  (hidden comment: CRCW02010000Z0ED)
R5  ValueDisplayed: 10k  [0402S]  (hidden comment: CRCW040210K0JNED)
R6  ValueDisplayed: 0  [0201L]  (hidden comment: CRCW02010000Z0ED)
R7  ValueDisplayed: 100  [0402S]  (hidden comment: CRCW0402100RJNED)
R8  ValueDisplayed: 10k  [0402S]  (hidden comment: CRCW040210K0JNED)
R9  ValueDisplayed: 0  [0402S]  (hidden comment: CRCW04020000Z0ED)
R10  ValueDisplayed: 0  [0201L]  (hidden comment: CRCW02010000Z0ED)
R11  ValueDisplayed: 10k  [0402S]  (hidden comment: CRCW040210K0JNED)
R20  ValueDisplayed: 0  [0201L]  (hidden comment: CRCW02010000Z0ED)
R29  ValueDisplayed: 49.9  [0402S]  (hidden comment: CRCW040249R9FKED)
R31  ValueDisplayed: 49.9  [0402S]  (hidden comment: CRCW040249R9FKED)
R33  ValueDisplayed: 49.9  [0402S]  (hidden comment: CRCW040249R9FKED)
R35  ValueDisplayed: 49.9  [0402S]  (hidden comment: CRCW040249R9FKED)
U1  PartNumber: LMX1205RHAT  [RHA0040C-MFG]  (hidden comment: LMX1205)

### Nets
CSB: U1.10(~{CS})
GND: C3.2 C4.2 C5.2 C6.2 C8.2 C9.2 C10.2 C11.2 C12.2 C13.2 C14.2 C15.2 C16.1 C21.1 C57.1 C58.1 C59.2 C60.2 C65.1 C66.1 C68.1 C69.1 C70.1 C71.1 J2.2 J2.3 J2.4 J2.5 J3.2 J3.3 J3.4 J3.5 J4.2 J4.3 J4.4 J4.5 J5.2 J5.3 J5.4 J5.5 J6.2 J6.3 J6.4 J6.5 J7.2 J7.3 J7.4 J7.5 J8.2 J8.3 J8.4 J8.5 J9.2 J9.3 J9.4 J9.5 J10.2 J10.3 J10.4 J10.5 J11.2 J11.3 J11.4 J11.5 J12.2 J12.3 J12.4 J12.5 J13.2 J13.3 J13.4 J13.5 J14.2 J14.3 J14.4 J14.5 J15.2 J15.3 J15.4 J15.5 J16.2 J16.3 J16.4 J16.5 J17.2 J17.3 J17.4 J17.5 J18.2 J18.3 J18.4 J18.5 J19.2 J19.3 J19.4 J19.5 J20.2 J20.3 J20.4 J20.5 J21.2 J21.3 J21.4 J21.5 J22.2 J22.3 J22.4 J22.5 J24.2 J24.3 J24.4 J24.5 J25.2 J25.3 J25.4 J25.5 J26.2 J26.3 J26.4 J26.5 R5.1 R11.1 U1.5(GND) U1.13(GND) U1.17(GND) U1.26(GND) U1.34(GND) U1.38(GND) U1.41(DAP)
SCK: U1.8(SCK)
SDI: U1.9(SDI)
SDO: U1.1(MUXOUT)
V0123: L1.1 L2.1
VLGC: C65.2 C66.2 L3.1 L4.1 L6.1 L7.1 R2.2 R8.2
C2N: C27.2 U1.32(CLKOUT2_N)
C2P: C29.2 U1.33(CLKOUT2_P)
LGCN: C26.2 R33.1 U1.27(LOGICLKOUT_N)
LGCP: C25.2 R29.2 U1.28(LOGICLKOUT_P)
LGSN: C30.2 R35.1 U1.23(LOGISYSREFOUT_N)
LGSP: C28.2 R31.2 U1.24(LOGISYSREFOUT_P)
S2N: C34.2 U1.29(SYSREFOUT2_N)
S2P: C32.2 U1.30(SYSREFOUT2_P)
NetC1_1: C1.1 J2.1
NetC1_2: C1.2 U1.14(CLKOUT0_N)
NetC2_1: C2.1 J3.1
NetC2_2: C2.2 U1.15(CLKOUT0_P)
NetC3_1: C3.1 C4.1 U1.31(BIAS23)
NetC5_1: C5.1 C6.1 U1.20(BIAS01)
NetC8_1: C8.1 C9.1 C70.2 L4.2 U1.25(VCC_LOGICLK)
NetC10_1: C10.1 C11.1 C71.2 L3.2 U1.4(VCC_CLKIN)
NetC12_1: C12.1 C13.1 C68.2 L2.2 U1.35(VCC23)
NetC14_1: C14.1 C15.1 C69.2 L1.2 U1.16(VCC01)
NetC16_2: C16.2 C58.2 C60.1 L7.2 R31.1 R35.2
NetC17_1: C17.1 U1.37(CLKOUT3_P)
NetC17_2: C17.2 J6.1
NetC18_1: C18.1 U1.36(CLKOUT3_N)
NetC18_2: C18.2 J7.1
NetC19_1: C19.1 J8.1
NetC19_2: C19.2 U1.19(CLKOUT1_P)
NetC20_1: C20.1 J9.1
NetC20_2: C20.2 U1.18(CLKOUT1_N)
NetC21_2: C21.2 C57.2 C59.1 L6.2 R29.1 R33.2
NetC23_1: C23.1 J12.1
NetC23_2: C23.2 U1.21(SYSREFOUT1_N)
NetC24_1: C24.1 J13.1
NetC24_2: C24.2 U1.22(SYSREFOUT1_P)
NetC25_1: C25.1 J14.1
NetC26_1: C26.1 J15.1
NetC27_1: C27.1 J16.1
NetC28_1: C28.1 J17.1
NetC29_1: C29.1 J18.1
NetC30_1: C30.1 J19.1
NetC31_1: C31.1 J20.1
NetC31_2: C31.2 U1.6(CLKIN_P)
NetC32_1: C32.1 J22.1
NetC33_1: C33.1 J24.1
NetC33_2: C33.2 U1.7(CLKIN_N)
NetC34_1: C34.1 J26.1
NetJ4_1: J4.1 R20.1
NetJ5_1: J5.1 R4.1
NetJ10_1: J10.1 R6.2
NetJ11_1: J11.1 R10.2
NetJ21_1: J21.1 R3.1
NetJ25_1: J25.1 R9.1
NetR2_1: R2.1 R7.1 R9.2 R11.2 U1.3(SYSREFREQ_N)
NetR3_2: R3.2 R5.2 R7.2 R8.1 U1.2(SYSREFREQ_P)
NetR4_2: R4.2 U1.12(SYSREFOUT0_P)
NetR6_1: R6.1 U1.40(SYSREFOUT3_P)
NetR10_1: R10.1 U1.39(SYSREFOUT3_N)
NetR20_2: R20.2 U1.11(SYSREFOUT0_N)

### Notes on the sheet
- !
- (near R20) DC-couple
- (near C6) C5 is a wideband capacitor
- DC-couple
- *** All 0.1µF capacitors on this page are wideband capacitors ***
- (near J19) Format
- (near J19) LVDS
- R31, R35
- DNP
- R32, R36
- (near J15) Format
- (near J15) LVDS
- R29, R33
- R30, R34
- CML
- 50Ω

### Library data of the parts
C1-C3 C8 C10 C12 C14 C16-C21 C23-C34 C57 C58 C65 C66 = CMP-0076713-1: CAP, CERM, 0.1 µF, 10 V,+/- 10%, X5R, 0201; Manufacturer: American Technical Ceramics; TaMin_C: -55°C; Polarized: N; SizeAreaWB_mm2: 2.08; U/M: EA; Value: 0.1uF; TaMax_C: 85°C; SizeZ_mm: 0.33; SizeX_mm: 0.6; SizeY_mm: 0.3; Cap_Case: 0201; Value2: 10V; SizeArea_mm2: 0.18; AEC Qualified: No; Cap_F: 100nF; AEC Category: Q200
C4 = CMP-0086193-1: CAP, CERM, 10 µF, 10 V,+/- 10%, X5R, 0603; Manufacturer: MuRata; SizeY_mm: 0.8; SizeAreaWB_mm2: 4.68; SizeX_mm: 1.6; SizeArea_mm2: 1.28; VDC_V: 10V; AEC Qualified: N; Cap_Case: 0603; Value: 10uF; U/M: EA; SizeZ_mm: 1; TaMax_C: 85°C; AEC Category: Q200; TaMin_C: -55°C
C5 = CMP-0009631-3: CAP, CERM, 10nF, 6.3 V, +100/-0%, C0G/NP0, 0201; Manufacturer: AT Ceramics; TaMin_C: -55°C; Polarized: N; SizeAreaWB_mm2: 2.08; Value1: Unknown; U/M: EA; Value: 0.01uF; TaMax_C: 125°C; Tolerance_%: 100%; SizeZ_mm: 0.33; SizeX_mm: 0.6; SizeY_mm: 0.3; Cap_Case: 0201; Value2: 6.3V; SizeArea_mm2: 0.18; AEC Category: Q200
C6 C9 C11 C13 C15 C59 C60 = CMP-0006608-2: CAP, CERM, 1 µF, 25 V, +/- 10%, X5R, 0402; Manufacturer: MuRata; TaMin_C: -55°C; Polarized: N; SizeAreaWB_mm2: 3; Value1: Unknown; U/M: EA; Value: 1uF; TaMax_C: 85°C; SizeZ_mm: 0.6; SizeX_mm: 1; SizeY_mm: 0.5; Cap_Case: 0402; Value2: 25V; AEC Category: Q200
C68-C71 = CMP-0086193-1: as C51 on sheet LMX1205EVM_PWR
J2-J11 J20 J24 = CMP-0055835-1: Connector, End launch SMA 50 ohm, TH; Manufacturer: Cinch Connectivity; PartNumber: 142-0761-881; CNHeader: FALSE; Green_Lifecycle: Not Set; Green_REACh: Incomplete; CT: TRUE
J12 J13 J16 J18 J21 J22 J25 J26 = CMP-0055835-1: Connector, End launch SMA 50 ohm, TH; Manufacturer: Cinch Connectivity; PartNumber: 142-0761-881; Green_REACh: Incomplete; Green_Lifecycle: Not Set; CNHeader: FALSE; CT: TRUE
J14 J15 J17 J19 = CMP-0088000-4: as J23 on sheet LMX1205EVM_PWR
L1-L4 = CMP-0003352-2: as L5 on sheet LMX1205EVM_PWR
L6 L7 = CMP-0058614-1: Inductor, Multilayer, Air Core, 18 nH, 0.3 A, 0.36 ohm, SMD; Manufacturer: MuRata; Isat: 0.3A @ % inductance drop; Irms: 0.3A @ C rise; Green_Lifecycle: Active; SizeAreaWB_mm2: 3; DCR_ohm: 0.36; Green_REACh: Passed; Value: 18nH; Imax_A: 300mA; SizeZ_mm: 0.55; SizeX_mm: 1; SizeY_mm: 0.5; Value2: 0.3A; AEC Category: Q200
R2 R5 R8 R11 = CMP-0026825-5: RES, 10 k, 5%, 0.063 W, AEC-Q200 Grade 0, 0402; Manufacturer: Vishay-Dale; Power_W: 63mW; TempCo: 200 ppm/C; Value_Code: 10k0; Value: 10k; EIA_Code: E24; SizeX_mm: 1; SizeY_mm: 0.5; SizeZ_mm: 0.6; Value2: 0.063W; AEC Qualified: Y; VDC_V: 50V; AEC Category: Q200; AEC Grade: 0
R3 R9 = CMP-0026822-3: RES, 0, 5%, 0.063 W, AEC-Q200 Grade 0, 0402; Manufacturer: Vishay-Dale; Power_W: 63mW; TempCo: 200 ppm/C; Value_Code: 0000; Value: 0; EIA_Code: E24; SizeX_mm: 1; SizeY_mm: 0.5; SizeZ_mm: 0.6; Value2: 0.063W; AEC Qualified: Y; VDC_V: 50V; AEC Category: Q200
R4 R6 R10 R20 = CMP-0027008-4: RES, 0, 5%, 0.05 W, 0201; Manufacturer: Vishay-Dale; Power_W: 50mW; TempCo: ppm/C; Value_Code: 0000; Value: 0; EIA_Code: E24; SizeX_mm: 0.6; SizeY_mm: 0.3; SizeZ_mm: 0.26; Value2: 0.05W; SizeArea_mm2: 0.18; AEC Qualified: N; AEC Category: Q200
R7 = CMP-0026824-3: RES, 100, 5%, 0.063 W, AEC-Q200 Grade 0, 0402; Manufacturer: Vishay-Dale; Power_W: 63mW; TempCo: 200 ppm/C; Value_Code: 100R; Value: 100; EIA_Code: E24; SizeX_mm: 1; SizeY_mm: 0.5; SizeZ_mm: 0.6; Value2: 0.063W; AEC Qualified: Y; VDC_V: 50V; AEC Category: Q200; AEC Grade: 0
R29 R31 R33 R35 = CMP-0026404-2: RES, 49.9, 1%, 0.063 W, AEC-Q200 Grade 0, 0402; Manufacturer: Vishay-Dale; Power_W: 63mW; TempCo: 100 ppm/C; Value_Code: 49R9; Value: 49.9; EIA_Code: E96; SizeX_mm: 1; SizeY_mm: 0.5; SizeZ_mm: 0.6; Value2: 0.063W; AEC Qualified: Y; VDC_V: 50V; AEC Category: Q200; AEC Grade: 0
U1 = CMP-0120269-1: Low-Noise, High-Frequency JESD Buffer/Multiplier/Divider; Manufacturer: Texas Instruments; SizeZ_mm: 1mm; AEC Qualified: No; Interface: SPI; Max Frequency: 12.8GHz; Max Supply Voltage: 2.6V; Min Supply Voltage: 2.4V; Nominal Supply Current: 315-1100mA; Number Of Outputs: 4; Propagation Delay: 125ps; Standoff Height: 0mm; TaMax_C: +85°C; TaMin_C: -40°C; TJmax_C: +125°C

## Sheet LMX1205EVM_Hardware.SchDoc: Hardware
size Letter; Date: Not shown in title block; ApprovedBy: Not shown in title block; CheckedBy: Not shown in title block; Author: Not shown in title block; CompanyName: Not shown in title block; DrawnBy: Noel Fung; Engineer: Noel Fung; Organization: Not shown in title block; Address1: Not shown in title block; Address2: Not shown in title block; Address3: Not shown in title block; Address4: Not shown in title block; DocumentNumber: 4; Revision: Use project parameter SCH_Rev; SheetNumber: 4; SheetTotal: 4; PageSetup: Record=PageOptions¦CenterHorizontal=True¦CenterVertical=True¦PrintScale=1.00¦XCorrection=1.00¦YCorrection=1.00¦PrintKind=0¦BorderSize=5000000¦LeftOffset=0¦BottomOffset=0¦Orientation=2¦PaperLength=1000¦PaperWidth=1000¦Scale=100¦PaperSource=15¦PrintQuality=600¦MediaType=1¦DitherType=10¦PaperKind=Letter¦PrintScaleMode=1
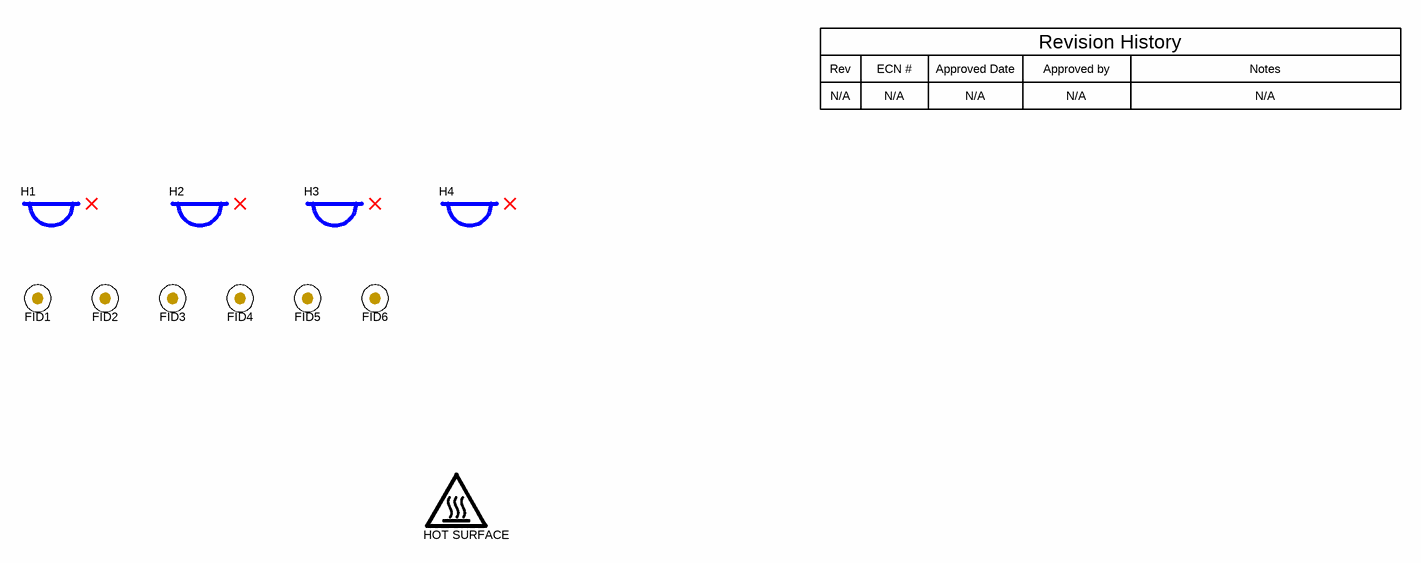
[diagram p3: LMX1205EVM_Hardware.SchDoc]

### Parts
FID1  Fiducial  [Fiducial10-20]  (value not drawn)
FID2  Fiducial  [Fiducial10-20]  (value not drawn)
FID3  Fiducial  [Fiducial10-20]  (value not drawn)
FID4  Fiducial  [Fiducial10-20]  (value not drawn)
FID5  Fiducial  [Fiducial10-20]  (value not drawn)
FID6  Fiducial  [Fiducial10-20]  (value not drawn)
H1  SJ61A6  [3M_SJ61A6]  (value not drawn)
H2  SJ61A6  [3M_SJ61A6]  (value not drawn)
H3  SJ61A6  [3M_SJ61A6]  (value not drawn)
H4  SJ61A6  [3M_SJ61A6]  (value not drawn)
Logo5  HOT SURFACE  [IEC_HotSurface_Small]  (no BOM)

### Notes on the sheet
- Rev
- N/A
- ECN #
- Approved Date
- Approved by
- Revision History
- Notes

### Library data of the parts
FID1-FID6 = CMP-0077181-1: Fiducial mark.  There is nothing to buy or mount.
H1-H4 = CMP-0079645-1: BUMPER CYLIN 0.312" DIA; Manufacturer: 3M; Green_Lifecycle: Not Set; Green_REACh: Incomplete
Logo5 = CMP-0074837-2: IEC 61010-1 Hot Surface Warning; PartNumber: CAUTION HOT SURFACE; Manufacturer: Texas Instruments; CompType: IC; AEC Category: Q200; SymbolCreator: a0412235

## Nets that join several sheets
CSB: LMX1205EVM_USB2ANY (R12.2 TP4.1), LMX1205EVM_BUF (U1.10)
GND: LMX1205EVM_USB2ANY (R24.2), LMX1205EVM_PWR (25 pins), LMX1205EVM_BUF (129 pins)
SCK: LMX1205EVM_USB2ANY (R13.2 TP5.1), LMX1205EVM_BUF (U1.8)
SDI: LMX1205EVM_USB2ANY (R14.2 TP6.1), LMX1205EVM_BUF (U1.9)
SDO: LMX1205EVM_USB2ANY (R16.2 TP1.1 U7.2), LMX1205EVM_BUF (U1.1)
V0123: LMX1205EVM_PWR (C53.2 C54.1 L5.2 TP7.1), LMX1205EVM_BUF (L1.1 L2.1)
VLGC: LMX1205EVM_PWR (C62.2 C63.1 L9.2 TP9.1), LMX1205EVM_BUF (8 pins)

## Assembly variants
001: not fitted C6 C68 C69 C70 C71 FID1 FID2 FID3 FID4 FID5 FID6 R2 R5 R7 R8 R11 R29 R30 R31 R32 R33 R34 R35 R36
